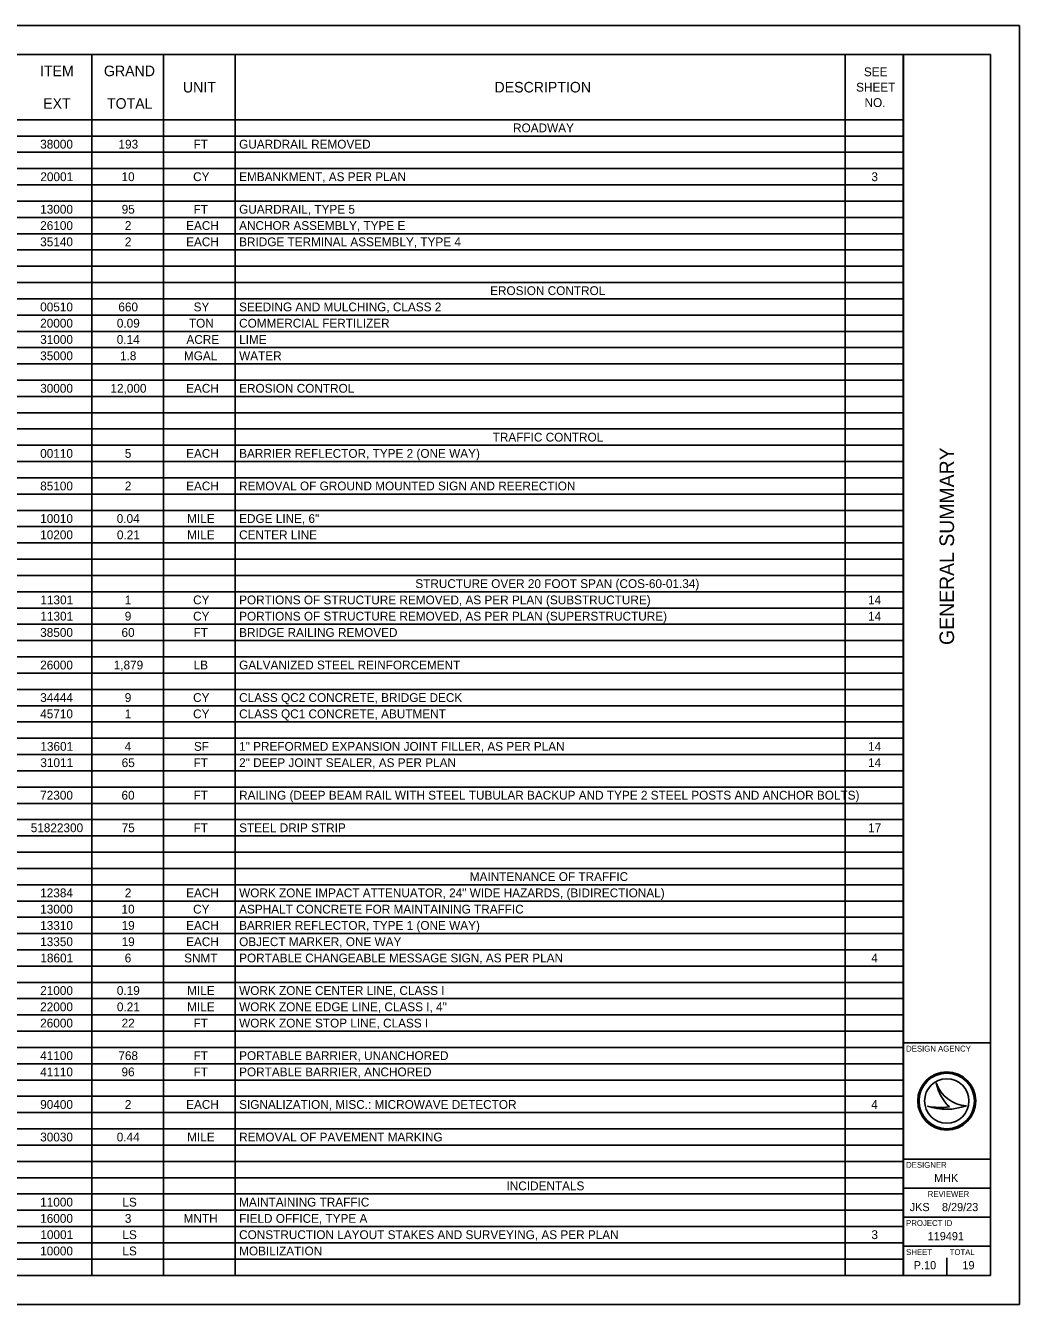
# Model space of a CAD drawing. Extents: x 0 to 34, y 0 to 22.
# Drawn here: x 16.9 to 34, y 0 to 22 of the extents above; entities that cross this region are included whole.
import ezdxf

# ---------------------------------------------------------------- set-up
doc = ezdxf.new("R2010")
doc.units = 0
for name, color, linetype in [('Default', 7, 'Continuous'), ('SH_Border', 7, 'Continuous'), ('SH_Cut_Line', 7, 'Continuous'), ('SH_Data', 7, 'Continuous')]:
    doc.layers.add(name, color=color, linetype=linetype)

msp = doc.modelspace()

# ---------------------------------------------------------------- linework, layer by layer
at = {"layer": 'Default'}
for p, q in [((1.5, 21.5), (32.004, 21.5)), ((18.036, 21.5), (18.036, 0.5)), ((19.272, 21.5), (19.272, 0.5)), ((20.507, 21.5), (20.507, 0.5)), ((30.999, 21.5), (30.999, 0.5)), ((32.004, 21.5), (32.004, 0.5)), ((1.5, 20.38), (32.004, 20.38)), ((1.5, 20.1), (32.004, 20.1)), ((1.5, 19.82), (32.004, 19.82)), ((1.5, 19.54), (32.004, 19.54)), ((1.5, 19.26), (32.004, 19.26)), ((1.5, 18.98), (32.004, 18.98)), ((1.5, 18.7), (32.004, 18.7)), ((1.5, 18.42), (32.004, 18.42)), ((1.5, 18.14), (32.004, 18.14)), ((1.5, 17.86), (32.004, 17.86)), ((1.5, 17.58), (32.004, 17.58)), ((1.5, 17.3), (32.004, 17.3)), ((1.5, 17.02), (32.004, 17.02)), ((1.5, 16.74), (32.004, 16.74)), ((1.5, 16.46), (32.004, 16.46)), ((1.5, 16.18), (32.004, 16.18)), ((1.5, 15.9), (32.004, 15.9)), ((1.5, 15.62), (32.004, 15.62)), ((1.5, 15.34), (32.004, 15.34)), ((1.5, 15.06), (32.004, 15.06)), ((1.5, 14.78), (32.004, 14.78)), ((1.5, 14.5), (32.004, 14.5)), ((1.5, 14.22), (32.004, 14.22)), ((1.5, 13.94), (32.004, 13.94)), ((1.5, 13.66), (32.004, 13.66)), ((1.5, 13.38), (32.004, 13.38)), ((1.5, 13.1), (32.004, 13.1)), ((1.5, 12.82), (32.004, 12.82)), ((1.5, 12.54), (32.004, 12.54)), ((1.5, 12.26), (32.004, 12.26)), ((1.5, 11.98), (32.004, 11.98)), ((1.5, 11.7), (32.004, 11.7)), ((1.5, 11.42), (32.004, 11.42)), ((1.5, 11.14), (32.004, 11.14)), ((1.5, 10.86), (32.004, 10.86)), ((1.5, 10.58), (32.004, 10.58)), ((1.5, 10.3), (32.004, 10.3)), ((1.5, 10.02), (32.004, 10.02)), ((1.5, 9.74), (32.004, 9.74)), ((1.5, 9.46), (32.004, 9.46)), ((1.5, 9.18), (32.004, 9.18)), ((1.5, 8.9), (32.004, 8.9)), ((1.5, 8.62), (32.004, 8.62)), ((1.5, 8.34), (32.004, 8.34)), ((1.5, 8.06), (32.004, 8.06)), ((1.5, 7.78), (32.004, 7.78)), ((1.5, 7.5), (32.004, 7.5)), ((1.5, 7.22), (32.004, 7.22)), ((1.5, 6.94), (32.004, 6.94)), ((1.5, 6.66), (32.004, 6.66)), ((1.5, 6.38), (32.004, 6.38)), ((1.5, 6.1), (32.004, 6.1)), ((1.5, 5.82), (32.004, 5.82)), ((1.5, 5.54), (32.004, 5.54)), ((1.5, 5.26), (32.004, 5.26)), ((1.5, 4.98), (32.004, 4.98)), ((1.5, 4.7), (32.004, 4.7)), ((1.5, 4.42), (32.004, 4.42)), ((1.5, 4.14), (32.004, 4.14)), ((1.5, 3.86), (32.004, 3.86)), ((1.5, 3.58), (32.004, 3.58)), ((1.5, 3.3), (32.004, 3.3)), ((1.5, 3.02), (32.004, 3.02)), ((1.5, 2.74), (32.004, 2.74)), ((1.5, 2.46), (32.004, 2.46)), ((1.5, 2.18), (32.004, 2.18)), ((1.5, 1.9), (32.004, 1.9)), ((1.5, 1.62), (32.004, 1.62)), ((1.5, 1.34), (32.004, 1.34)), ((1.5, 1.06), (32.004, 1.06)), ((1.5, 0.78), (32.004, 0.78)), ((1.5, 0.5), (32.004, 0.5))]:
    msp.add_line(p, q, dxfattribs=at)
at = {"layer": 'SH_Border'}
for p, q in [((32, 0.5), (32, 21.5)), ((32, 4.5), (33.5, 4.5)), ((32, 2.5), (33.5, 2.5)), ((32, 2), (33.5, 2)), ((32, 1.5), (33.5, 1.5)), ((32, 1), (33.5, 1))]:
    msp.add_line(p, q, dxfattribs=at)
msp.add_lwpolyline([(1.5, 21.5), (33.5, 21.5), (33.5, 0.5), (1.5, 0.5)], close=True, dxfattribs=at)
at = {"layer": 'SH_Cut_Line'}
msp.add_lwpolyline([(0, 0), (34, 0), (34, 22), (0, 22)], close=True, dxfattribs=at)
at = {"layer": 'SH_Data'}
for p, q in [((32.567, 3.81), (32.567, 3.81)), ((32.417, 3.41), (32.417, 3.41)), ((32.75, 3.5), (32.75, 3.5)), ((33.087, 3.419), (33.087, 3.419)), ((32.375, 0.675), (32.375, 0.675)), ((32.75, 0.5), (32.75, 0.8))]:
    msp.add_line(p, q, dxfattribs=at)
for radius in [0.5, 0.477, 0.477, 0.382]:
    msp.add_circle((32.75, 3.5), radius, dxfattribs=at)
for centre, radius, start, end in [((33.116, 3.998), 0.58, 198.9257, 198.9319), ((33.347, 3.97), 0.796, 191.6379, 191.6421), ((33.116, 3.998), 0.58, 198.9319, 267.1657), ((33.347, 3.97), 0.796, 191.6421, 226.0947), ((32.739, 4.37), 1.013, 251.4576, 290.0832), ((32.648, 4.654), 1.266, 259.4964, 259.4995), ((32.739, 4.37), 1.013, 251.4527, 251.4576), ((32.648, 4.654), 1.266, 259.4995, 276.6672)]:
    msp.add_arc(centre, radius, start, end, dxfattribs=at)

# ---------------------------------------------------------------- texts
at = {"layer": 'Default'}
for s, height, p in [('ITEM', 0.1818, (17.147, 21.129)), ('GRAND', 0.1818, (18.247, 21.129)), ('SEE ', 0.1515, (31.324, 21.129)), ('UNIT', 0.1818, (19.606, 20.849)), ('DESCRIPTION', 0.18184, (24.967, 20.849)), ('SHEET ', 0.1515, (31.19, 20.864)), ('EXT', 0.1818, (17.201, 20.569)), ('TOTAL', 0.1818, (18.299, 20.569)), ('NO.', 0.1515, (31.335, 20.599)), ('ROADWAY', 0.1515, (25.287, 20.164)), ('38000', 0.1515, (17.15, 19.884)), ('193', 0.1515, (18.497, 19.884)), ('FT', 0.1515, (19.789, 19.884)), ('GUARDRAIL REMOVED', 0.15153, (20.573, 19.884)), ('20001', 0.1515, (17.153, 19.324)), ('10', 0.1515, (18.549, 19.324)), ('CY', 0.1515, (19.781, 19.324)), ('EMBANKMENT, AS PER PLAN', 0.15153, (20.573, 19.324)), ('3', 0.152, (31.453, 19.324)), ('13000', 0.1515, (17.15, 18.764)), ('95', 0.1515, (18.552, 18.764)), ('FT', 0.1515, (19.789, 18.764)), ('GUARDRAIL, TYPE 5', 0.15153, (20.573, 18.764)), ('26100', 0.1515, (17.15, 18.484)), ('2', 0.152, (18.606, 18.484)), ('EACH', 0.1515, (19.661, 18.484)), ('ANCHOR ASSEMBLY, TYPE E', 0.15153, (20.573, 18.484)), ('35140', 0.1515, (17.15, 18.204)), ('2', 0.152, (18.606, 18.204)), ('EACH', 0.1515, (19.661, 18.204)), ('BRIDGE TERMINAL ASSEMBLY, TYPE 4', 0.15153, (20.573, 18.204)), ('EROSION CONTROL', 0.15153, (24.892, 17.364)), ('00510', 0.1515, (17.15, 17.084)), ('660', 0.1515, (18.495, 17.084)), ('SY', 0.1515, (19.79, 17.084)), ('SEEDING AND MULCHING, CLASS 2', 0.15153, (20.573, 17.084)), ('20000', 0.1515, (17.15, 16.804)), ('0.09', 0.1515, (18.469, 16.804)), ('TON', 0.1515, (19.709, 16.804)), ('COMMERCIAL FERTILIZER', 0.15153, (20.573, 16.804)), ('31000', 0.1515, (17.15, 16.524)), ('0.14', 0.1515, (18.467, 16.524)), ('ACRE', 0.1515, (19.666, 16.524)), ('LIME', 0.1515, (20.573, 16.524)), ('35000', 0.1515, (17.15, 16.244)), ('1.8', 0.1515, (18.523, 16.244)), ('MGAL', 0.1515, (19.623, 16.244)), ('WATER', 0.1515, (20.573, 16.244)), ('30000', 0.1515, (17.15, 15.684)), ('12,000', 0.1515, (18.359, 15.684)), ('EACH', 0.1515, (19.661, 15.684)), ('EROSION CONTROL', 0.15153, (20.573, 15.684)), ('TRAFFIC CONTROL', 0.15153, (24.936, 14.844)), ('00110', 0.1515, (17.15, 14.564)), ('5', 0.152, (18.606, 14.564)), ('EACH', 0.1515, (19.661, 14.564)), ('BARRIER REFLECTOR, TYPE 2 (ONE WAY)', 0.15153, (20.573, 14.564)), ('85100', 0.1515, (17.15, 14.004)), ('2', 0.152, (18.606, 14.004)), ('EACH', 0.1515, (19.661, 14.004)), ('REMOVAL OF GROUND MOUNTED SIGN AND REERECTION', 0.15153, (20.573, 14.004)), ('10010', 0.1515, (17.15, 13.444)), ('0.04', 0.1515, (18.467, 13.444)), ('MILE', 0.1515, (19.679, 13.444)), ('EDGE LINE, 6"', 0.15153, (20.573, 13.444)), ('10200', 0.1515, (17.15, 13.164)), ('0.21', 0.1515, (18.47, 13.164)), ('MILE', 0.1515, (19.679, 13.164)), ('CENTER LINE', 0.15153, (20.573, 13.164)), ('STRUCTURE OVER 20 FOOT SPAN (COS-60-01.34)', 0.15153, (23.605, 12.324)), ('11301', 0.1515, (17.153, 12.044)), ('1', 0.152, (18.606, 12.044)), ('CY', 0.1515, (19.781, 12.044)), ('PORTIONS OF STRUCTURE REMOVED, AS PER PLAN (SUBSTRUCTURE)', 0.15153, (20.573, 12.044)), ('14', 0.1515, (31.395, 12.044)), ('11301', 0.1515, (17.153, 11.764)), ('9', 0.152, (18.605, 11.764)), ('CY', 0.1515, (19.781, 11.764)), ('PORTIONS OF STRUCTURE REMOVED, AS PER PLAN (SUPERSTRUCTURE)', 0.15153, (20.573, 11.764)), ('14', 0.1515, (31.395, 11.764)), ('38500', 0.1515, (17.15, 11.484)), ('60', 0.1515, (18.549, 11.484)), ('FT', 0.1515, (19.789, 11.484)), ('BRIDGE RAILING REMOVED', 0.15153, (20.573, 11.484)), ('26000', 0.1515, (17.15, 10.924)), ('1,879', 0.1515, (18.415, 10.924)), ('LB', 0.1515, (19.79, 10.924)), ('GALVANIZED STEEL REINFORCEMENT', 0.15153, (20.573, 10.924)), ('34444', 0.1515, (17.15, 10.364)), ('9', 0.152, (18.605, 10.364)), ('CY', 0.1515, (19.781, 10.364)), ('CLASS QC2 CONCRETE, BRIDGE DECK', 0.15153, (20.573, 10.364)), ('45710', 0.1515, (17.15, 10.084)), ('1', 0.152, (18.606, 10.084)), ('CY', 0.1515, (19.781, 10.084)), ('CLASS QC1 CONCRETE, ABUTMENT', 0.15153, (20.573, 10.084)), ('13601', 0.1515, (17.153, 9.524)), ('4', 0.152, (18.603, 9.524)), ('SF', 0.1515, (19.795, 9.524)), ('1" PREFORMED EXPANSION JOINT FILLER, AS PER PLAN', 0.15153, (20.573, 9.524)), ('14', 0.1515, (31.395, 9.524)), ('31011', 0.1515, (17.153, 9.244)), ('65', 0.1515, (18.552, 9.244)), ('FT', 0.1515, (19.789, 9.244)), ('2" DEEP JOINT SEALER, AS PER PLAN', 0.15153, (20.573, 9.244)), ('14', 0.1515, (31.395, 9.244)), ('72300', 0.1515, (17.15, 8.684)), ('60', 0.1515, (18.549, 8.684)), ('FT', 0.1515, (19.789, 8.684)), ('RAILING (DEEP BEAM RAIL WITH STEEL TUBULAR BACKUP AND TYPE 2 STEEL POSTS AND ANCHOR BOLTS)', 0.15153, (20.573, 8.684)), ('51822300', 0.1515, (16.987, 8.124)), ('75', 0.1515, (18.552, 8.124)), ('FT', 0.1515, (19.789, 8.124)), ('STEEL DRIP STRIP', 0.15153, (20.573, 8.124)), ('17', 0.1515, (31.397, 8.124)), ('MAINTENANCE OF TRAFFIC', 0.15153, (24.542, 7.284)), ('12384', 0.1515, (17.15, 7.004)), ('2', 0.152, (18.606, 7.004)), ('EACH', 0.1515, (19.661, 7.004)), ('WORK ZONE IMPACT ATTENUATOR, 24" WIDE HAZARDS, (BIDIRECTIONAL)', 0.15153, (20.573, 7.004)), ('13000', 0.1515, (17.15, 6.724)), ('10', 0.1515, (18.549, 6.724)), ('CY', 0.1515, (19.781, 6.724)), ('ASPHALT CONCRETE FOR MAINTAINING TRAFFIC', 0.15153, (20.573, 6.724)), ('BARRIER REFLECTOR, TYPE 1 (ONE WAY)', 0.15153, (20.573, 6.444)), ('13310', 0.1515, (17.15, 6.444)), ('19', 0.1515, (18.551, 6.444)), ('EACH', 0.1515, (19.661, 6.444)), ('13350', 0.1515, (17.15, 6.164)), ('19', 0.1515, (18.551, 6.164)), ('EACH', 0.1515, (19.661, 6.164)), ('OBJECT MARKER, ONE WAY', 0.15153, (20.573, 6.164)), ('18601', 0.1515, (17.153, 5.884)), ('6', 0.152, (18.604, 5.884)), ('SNMT', 0.1515, (19.627, 5.884)), ('PORTABLE CHANGEABLE MESSAGE SIGN, AS PER PLAN', 0.15153, (20.573, 5.884)), ('4', 0.152, (31.45, 5.884)), ('21000', 0.1515, (17.15, 5.324)), ('0.19', 0.1515, (18.469, 5.324)), ('MILE', 0.1515, (19.679, 5.324)), ('WORK ZONE CENTER LINE, CLASS I', 0.15153, (20.573, 5.324)), ('22000', 0.1515, (17.15, 5.044)), ('0.21', 0.1515, (18.47, 5.044)), ('MILE', 0.1515, (19.679, 5.044)), ('WORK ZONE EDGE LINE, CLASS I, 4"', 0.15153, (20.573, 5.044)), ('26000', 0.1515, (17.15, 4.764)), ('22', 0.1515, (18.551, 4.764)), ('FT', 0.1515, (19.789, 4.764)), ('WORK ZONE STOP LINE, CLASS I', 0.15153, (20.573, 4.764)), ('41100', 0.1515, (17.15, 4.204)), ('768', 0.1515, (18.495, 4.204)), ('FT', 0.1515, (19.789, 4.204)), ('PORTABLE BARRIER, UNANCHORED', 0.15153, (20.573, 4.204)), ('41110', 0.1515, (17.15, 3.924)), ('96', 0.1515, (18.549, 3.924)), ('FT', 0.1515, (19.789, 3.924)), ('PORTABLE BARRIER, ANCHORED', 0.15153, (20.573, 3.924)), ('90400', 0.1515, (17.15, 3.364)), ('2', 0.152, (18.606, 3.364)), ('EACH', 0.1515, (19.661, 3.364)), ('SIGNALIZATION, MISC.: MICROWAVE DETECTOR', 0.15153, (20.573, 3.364)), ('4', 0.152, (31.45, 3.364)), ('30030', 0.1515, (17.15, 2.804)), ('0.44', 0.1515, (18.467, 2.804)), ('MILE', 0.1515, (19.679, 2.804)), ('REMOVAL OF PAVEMENT MARKING', 0.15153, (20.573, 2.804)), ('INCIDENTALS', 0.15153, (25.174, 1.964)), ('11000', 0.1515, (17.15, 1.684)), ('LS', 0.1515, (18.564, 1.684)), ('MAINTAINING TRAFFIC', 0.15153, (20.573, 1.684)), ('16000', 0.1515, (17.15, 1.404)), ('3', 0.152, (18.606, 1.404)), ('MNTH', 0.1515, (19.618, 1.404)), ('FIELD OFFICE, TYPE A', 0.15153, (20.573, 1.404)), ('10001', 0.1515, (17.153, 1.124)), ('LS', 0.1515, (18.564, 1.124)), ('CONSTRUCTION LAYOUT STAKES AND SURVEYING, AS PER PLAN', 0.15153, (20.573, 1.124)), ('3', 0.152, (31.453, 1.124)), ('10000', 0.1515, (17.15, 0.844)), ('LS', 0.1515, (18.564, 0.844)), ('MOBILIZATION', 0.15153, (20.573, 0.844))]:
    msp.add_text(s, height=height, dxfattribs=at).set_placement(p)
at = {"layer": 'SH_Data'}
msp.add_text('GENERAL SUMMARY', height=0.25, rotation=90, dxfattribs=at).set_placement((32.875, 11.344))
for s, height, p in [('DESIGN AGENCY', 0.1, (32.05, 4.35)), ('DESIGNER', 0.1, (32.05, 2.35)), ('MHK', 0.14, (32.532, 2.105)), ('REVIEWER', 0.1, (32.422, 1.85)), ('JKS', 0.14, (32.112, 1.605)), ('8/29/23', 0.14, (32.667, 1.605)), ('PROJECT ID', 0.1, (32.05, 1.35)), ('119491', 0.14, (32.421, 1.105)), ('SHEET', 0.1, (32.05, 0.85)), ('TOTAL', 0.1, (32.8, 0.85)), ('P.10', 0.14, (32.182, 0.605)), ('19', 0.14, (33.019, 0.605))]:
    msp.add_text(s, height=height, dxfattribs=at).set_placement(p)

doc.saveas('drawing.dxf')
